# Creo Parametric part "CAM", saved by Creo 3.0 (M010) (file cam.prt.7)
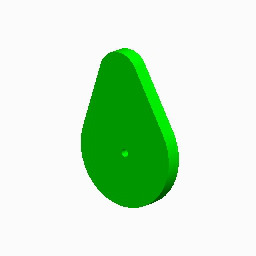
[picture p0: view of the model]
Units: millimeter Newton Second (mmNs); MM, TONNE, SECS

Created from: INLBS_PART_SOLID.PRT

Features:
  1. datum plane "RIGHT"
  2. datum plane "TOP"
  3. datum plane "FRONT"
  4. coordinate system
  5. extrusion "Extrude 1"

Surfaces: 7 plane, 4 cylinder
